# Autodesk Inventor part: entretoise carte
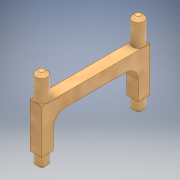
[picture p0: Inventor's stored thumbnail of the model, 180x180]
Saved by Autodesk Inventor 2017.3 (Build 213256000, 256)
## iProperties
Part Number: entretoise carte
Material: Plastique ABS
Document SubType Name: Modeling
Designer: ficho
Density: 1.06 g/cm^3
Appearance: Pin jaune - Massif moiré clair faible lustre
Author: ficho
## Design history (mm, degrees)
sketch "Esquisse1"
  geometry: C1 r 0.9 at (0, 0); C2 r 0.9 at (0, 15.24); 1 further point
  constraints: 2 centre point, 1 coincident
  dimensions: "d0" = 1.8 diameter of C1; "d1" = 1.8 diameter of C2; "d2" = 15.24 distance of point (0, 0) C2.centre
extrude "Extrusion1" new body sketch "Esquisse1" distance "d3" = 4; taper "d4" = 0 deg
chamfer "Chanfrein1" distance "d5" = 0.5; stored, may be unused: second distance "d6" = 2, angle "d7" = 45 deg
sketch "Esquisse2"
  geometry: L1 (-0.9, 0.9)-(0.9, 0.9); L2 (0.9, 0.9)-(0.9, -16.14); L3 (0.9, -16.14)-(-0.9, -16.14); L4 (-0.9, -16.14)-(-0.9, 0.9); 1 further point
  constraints: 8 end point, 2 parallel, 1 horizontal, 1 perpendicular
extrude "Extrusion2" join sketch "Esquisse2" distance "d8" = 2; taper "d9" = 0 deg
sketch "Esquisse3"
  geometry: L1 (0.9, 0)-(0.9, -15.24) reference; L2 (-0.9, 0.9)-(0.9, 0.9); L3 (0.9, 0.9)-(0.9, -0.9); L4 (0.9, -0.9)-(-0.9, -0.9); L5 (-0.9, -0.9)-(-0.9, 0.9); L6 (-0.9, 0.9)-(-0.9, -16.14) reference; L7 (-0.9, -14.34)-(0.9, -14.34); L8 (0.9, -14.34)-(0.9, -16.14); L9 (0.9, -16.14)-(-0.9, -16.14); L10 (-0.9, -16.14)-(-0.9, -14.34); C1 r 0.4 at (0, 0) reference; 1 further point
  constraints: 16 end point, 4 parallel, 3 point on line, 2 horizontal, 2 perpendicular
extrude "Extrusion3" join sketch "Esquisse3" distance "d10" = 5; taper "d11" = 0 deg
sketch "Esquisse4"
  geometry: C1 r 0.9 at (0, 0) reference; C2 r 0.9 at (0, 0); C3 r 0.9 at (0, 15.24); 1 further point
  constraints: 2 centre point, 1 coincident
extrude "Extrusion4" join sketch "Esquisse4" distance "d12" = 2; taper "d13" = 0 deg
fillet "Congé1" dims "d14" = 2
chamfer "Chanfrein2" distance "d15" = 0.5; stored, may be unused: second distance "d16" = 2, angle "d17" = 45 deg
node "Solide1"
